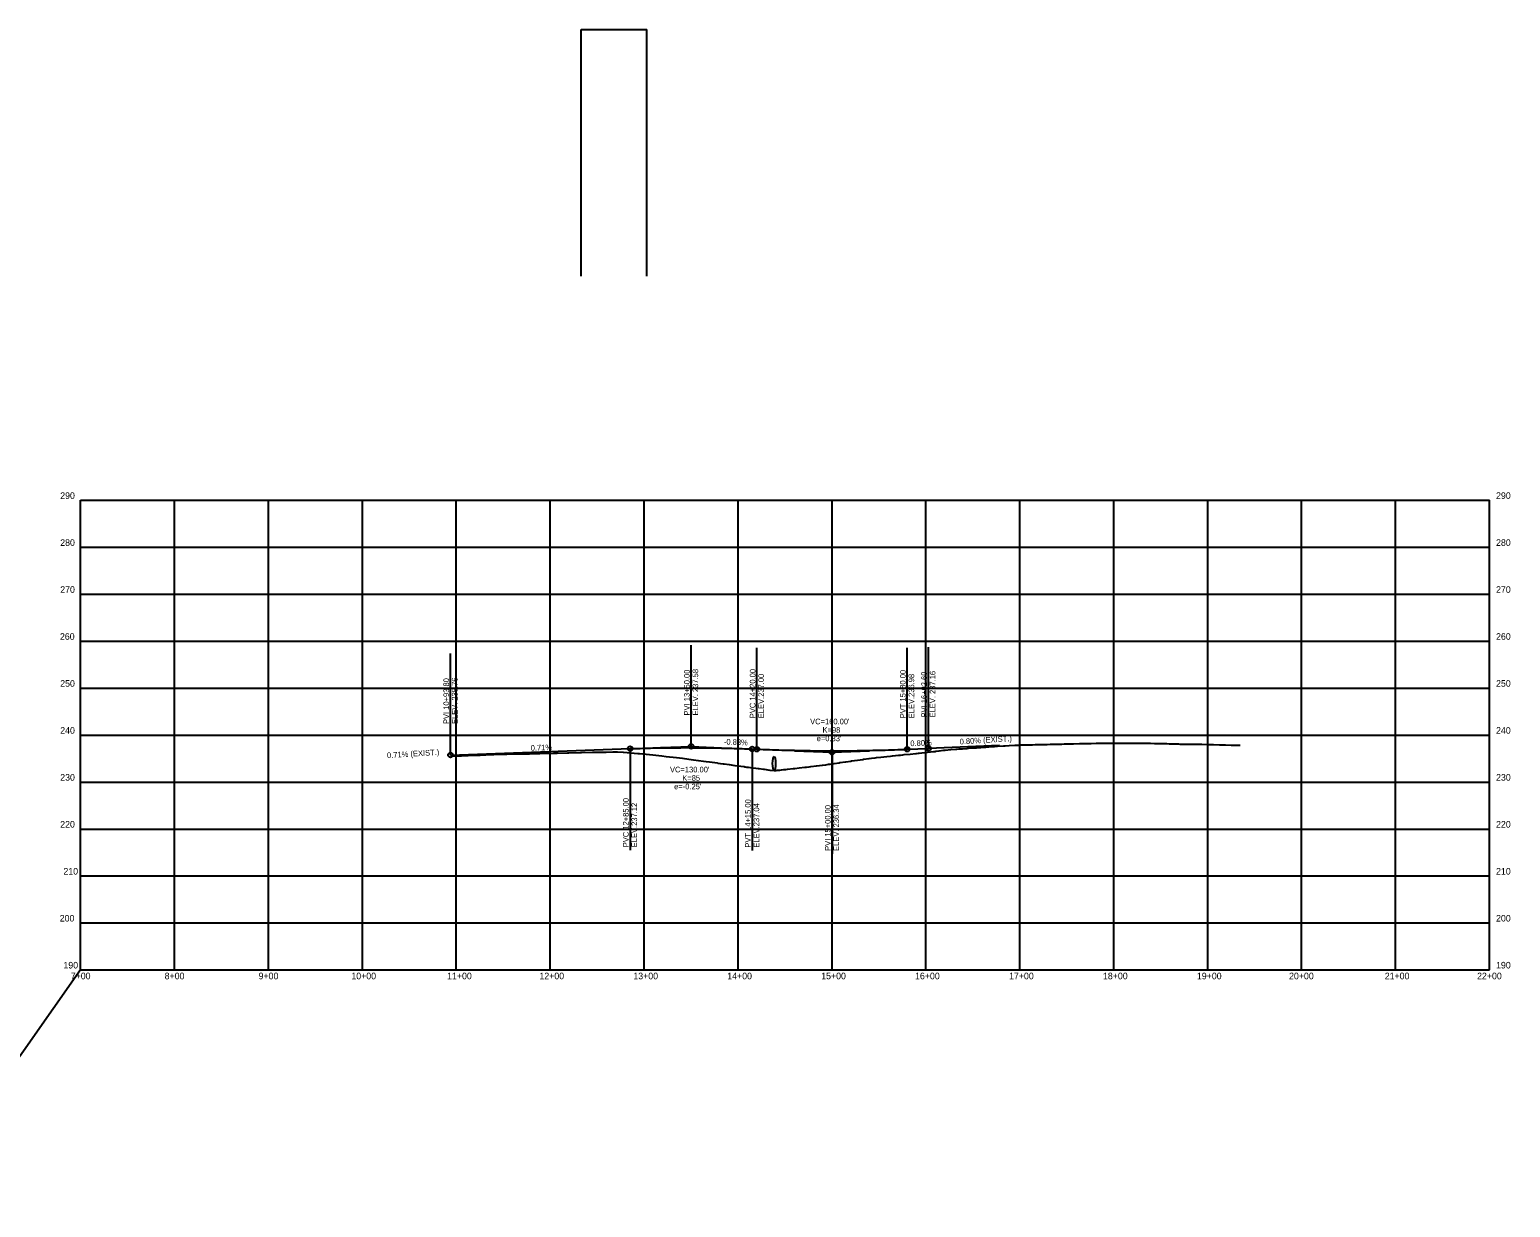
# Model space of a CAD drawing. Extents: x 1676565 to 1681112, y 227357 to 229815.
# Drawn here: x 1678113 to 1679690, y 227357 to 228611 of the extents above; entities that cross this region are included whole.
import ezdxf

# ---------------------------------------------------------------- set-up
doc = ezdxf.new("R2010")
doc.units = 0
for name, color, linetype in [('B_Steel', 7, 'Continuous'), ('R_Axis', 7, 'Continuous'), ('R_Axis Annot', 7, 'Continuous'), ('R_Exist Surface', 7, 'Continuous'), ('R_Grid', 7, 'Continuous'), ('R_Horz Alg Annot', 7, 'Continuous'), ('R_No Plot', 7, 'Continuous'), ('R_Vert Alg', 7, 'Continuous'), ('R_Vert Alg Annot', 7, 'Continuous'), ('R_Water', 7, 'Continuous')]:
    doc.layers.add(name, color=color, linetype=linetype)

msp = doc.modelspace()

# ---------------------------------------------------------------- linework, layer by layer
at = {"layer": 'B_Steel'}
for p, q in [((1678700.3, 228348.8), (1678700.3, 228611.2)), ((1678700.3, 228611.2), (1678770.3, 228611.2)), ((1678770.3, 228348.8), (1678770.3, 228611.2))]:
    msp.add_line(p, q, dxfattribs=at)
at = {"layer": 'R_Axis'}
for p, q in [((1678167.3, 227610), (1678167.3, 228110)), ((1679667.3, 227610), (1679667.3, 228110)), ((1678167.3, 227610), (1679667.3, 227610))]:
    msp.add_line(p, q, dxfattribs=at)
at = {"layer": 'R_Exist Surface'}
msp.add_lwpolyline([(1678561.1, 227837.6), (1678565.7, 227837.8), (1678573, 227838), (1678580.1, 227838.3), (1678586, 227838.5), (1678592.7, 227838.8), (1678598.9, 227839.1), (1678607.4, 227839.3), (1678617, 227839.7), (1678621, 227839.7), (1678628, 227839.9), (1678633.4, 227840), (1678638.4, 227840.1), (1678645.4, 227840.1), (1678656.1, 227840.4), (1678670.8, 227840.7), (1678674.7, 227840.8), (1678685.8, 227841), (1678687.2, 227841.1), (1678699.5, 227841.4), (1678699.7, 227841.4), (1678700.7, 227841.4), (1678712.2, 227841.7), (1678727, 227842), (1678734.1, 227842.2), (1678738.8, 227842.3), (1678744.9, 227841.8), (1678745.3, 227841.8), (1678760.7, 227840.5), (1678762.5, 227840.3), (1678776.4, 227839), (1678779.8, 227838.6), (1678786.2, 227837.9), (1678790.7, 227837.3), (1678801.8, 227836.1), (1678808, 227835.4), (1678814.7, 227834.4), (1678820, 227833.7), (1678830.4, 227832.4), (1678833.4, 227832), (1678837, 227831.5), (1678845.3, 227830.3), (1678845.7, 227830.2), (1678851.5, 227829.5), (1678852.6, 227829.4), (1678857.7, 227828.6), (1678863.9, 227827.7), (1678870.1, 227826.9), (1678873.9, 227826.4), (1678874.4, 227826.3), (1678874.9, 227826.2), (1678876.4, 227826), (1678878.4, 227825.7), (1678882.6, 227825.2), (1678886.2, 227824.8), (1678888.8, 227824.5), (1678889.6, 227824.4), (1678894.4, 227823.7), (1678895, 227823.7), (1678901.2, 227822.8), (1678905.6, 227822.3), (1678907.4, 227822.4), (1678908.4, 227822.5), (1678911.7, 227822.8), (1678913.7, 227823), (1678915.5, 227823.2), (1678918.2, 227823.5), (1678919.9, 227823.7), (1678926.1, 227824.3), (1678926.3, 227824.3), (1678927.8, 227824.6), (1678932.3, 227825), (1678938.5, 227825.7), (1678940.3, 227825.8), (1678943.1, 227826.3), (1678944.7, 227826.5), (1678950.9, 227827.3), (1678957.2, 227828.1), (1678960.6, 227828.5), (1678963.4, 227828.9), (1678965.5, 227829.2), (1678969.6, 227829.8), (1678975.1, 227830.5), (1678975.8, 227830.7), (1678981.7, 227831.5), (1678982, 227831.6), (1678987.3, 227832.3), (1678988.2, 227832.5), (1678994.5, 227833.3), (1679000.3, 227834.1), (1679000.7, 227834.2), (1679006.9, 227835), (1679009.3, 227835.3), (1679013.1, 227835.8), (1679014.8, 227836.1), (1679019.3, 227836.6), (1679025.5, 227837.2), (1679029.6, 227837.6), (1679031.7, 227837.9), (1679031.8, 227837.9), (1679038, 227838.5), (1679040.3, 227838.7), (1679042.8, 227839), (1679044.2, 227839.2), (1679050.4, 227839.8), (1679056.6, 227840.4), (1679057.1, 227840.4), (1679059.3, 227840.7), (1679060.1, 227840.8), (1679062.8, 227841.1), (1679069, 227841.8), (1679075.3, 227842.5), (1679077.2, 227842.7), (1679077.8, 227842.8), (1679081.5, 227843.3), (1679086, 227843.8), (1679086.8, 227843.9), (1679087, 227843.9), (1679087.7, 227843.9), (1679093.9, 227844.5), (1679099, 227844.9), (1679100.1, 227845), (1679102.5, 227845.2), (1679106.3, 227845.5), (1679111.2, 227845.9), (1679112.6, 227846), (1679117.7, 227846.3), (1679118.8, 227846.4), (1679121, 227846.6), (1679125, 227846.8), (1679125.7, 227846.9), (1679131.2, 227847.3), (1679137.4, 227847.8), (1679140.3, 227848), (1679141.9, 227848.1), (1679143.6, 227848.2), (1679149.9, 227848.6), (1679151.1, 227848.7), (1679151.5, 227848.7), (1679155.8, 227849), (1679156.1, 227849), (1679162, 227849.2), (1679162.3, 227849.3), (1679166.9, 227849.4), (1679168.5, 227849.5), (1679173.7, 227849.6), (1679174.7, 227849.6), (1679177.6, 227849.6), (1679180.9, 227849.8), (1679183.5, 227849.9), (1679187.2, 227849.9), (1679191.7, 227850), (1679193.4, 227850.1), (1679196.3, 227850.1), (1679199.6, 227850.2), (1679205.1, 227850.3), (1679205.8, 227850.3), (1679212, 227850.5), (1679214.4, 227850.6), (1679218.2, 227850.6), (1679221.7, 227850.7), (1679224.4, 227850.7), (1679230.7, 227850.9), (1679233.3, 227850.9), (1679236.9, 227851), (1679242, 227851.1), (1679243.1, 227851.2), (1679248.5, 227851.3), (1679249.3, 227851.3), (1679255.2, 227851.4), (1679255.5, 227851.4), (1679261.7, 227851.4), (1679265.4, 227851.5), (1679268, 227851.5), (1679269, 227851.5), (1679274.2, 227851.5), (1679280.4, 227851.5), (1679284.1, 227851.5), (1679286.6, 227851.5), (1679287.3, 227851.5), (1679292.8, 227851.5), (1679295.1, 227851.5), (1679299, 227851.4), (1679305.3, 227851.3), (1679306.3, 227851.3), (1679310.7, 227851.2), (1679311.5, 227851.2), (1679317.7, 227851), (1679322.1, 227851), (1679323.9, 227850.9), (1679326.1, 227850.8), (1679330.1, 227850.7), (1679336.3, 227850.6), (1679337.6, 227850.5), (1679342.6, 227850.5), (1679348.8, 227850.4), (1679355, 227850.3), (1679355.5, 227850.3), (1679359.5, 227850.2), (1679361.2, 227850.2), (1679367.4, 227850.1), (1679368.4, 227850), (1679372.6, 227849.9), (1679373.6, 227849.9), (1679379.8, 227849.8), (1679385.9, 227849.6), (1679386.1, 227849.6), (1679392.3, 227849.4), (1679396.5, 227849.3), (1679399.9, 227849.2), (1679402, 227849.1)], dxfattribs=at)
at = {"layer": 'R_Grid'}
for p, q in [((1678167.3, 228110), (1679667.3, 228110)), ((1678167.3, 228110), (1679667.3, 228110)), ((1678267.3, 227610), (1678267.3, 228110)), ((1678367.3, 227610), (1678367.3, 228110)), ((1678467.3, 227610), (1678467.3, 228110)), ((1678567.3, 227610), (1678567.3, 228110)), ((1678667.3, 227610), (1678667.3, 228110)), ((1678767.3, 227610), (1678767.3, 228110)), ((1678867.3, 227610), (1678867.3, 228110)), ((1678967.3, 227610), (1678967.3, 228110)), ((1679067.3, 227610), (1679067.3, 228110)), ((1679167.3, 227610), (1679167.3, 228110)), ((1679267.3, 227610), (1679267.3, 228110)), ((1679367.3, 227610), (1679367.3, 228110)), ((1679467.3, 227610), (1679467.3, 228110)), ((1679567.3, 227610), (1679567.3, 228110)), ((1678167.3, 228060), (1679667.3, 228060)), ((1678167.3, 228010), (1679667.3, 228010)), ((1678167.3, 227960), (1679667.3, 227960)), ((1678167.3, 227910), (1679667.3, 227910)), ((1678167.3, 227860), (1679667.3, 227860)), ((1678167.3, 227810), (1679667.3, 227810)), ((1678167.3, 227760), (1679667.3, 227760)), ((1678167.3, 227710), (1679667.3, 227710)), ((1678167.3, 227660), (1679667.3, 227660))]:
    msp.add_line(p, q, dxfattribs=at)
at = {"layer": 'R_Horz Alg Annot'}
msp.add_line((1678561.1, 227838.9), (1678561.1, 227838.8), dxfattribs=at)
at = {"layer": 'R_No Plot'}
msp.add_line((1678167.3, 227610), (1677989.4, 227357.1), dxfattribs=at)
at = {"layer": 'R_Vert Alg'}
for p, q in [((1678561.1, 227838.8), (1678752.3, 227845.6)), ((1678784.8, 227846.7), (1678817.3, 227847.9)), ((1678817.3, 227847.9), (1678849.8, 227846.6)), ((1678882.3, 227845.2), (1678887.3, 227845)), ((1678927.3, 227843.3), (1678967.3, 227841.7)), ((1678967.3, 227841.7), (1679007.3, 227843.3)), ((1679047.3, 227844.9), (1679069.9, 227845.8)), ((1679145.5, 227848.8), (1679069.9, 227845.8))]:
    msp.add_line(p, q, dxfattribs=at)
for points in [[(1678752.3, 227845.6), (1678755, 227845.7), (1678757.7, 227845.8), (1678760.4, 227845.9), (1678763.1, 227845.9), (1678765.8, 227846), (1678767.3, 227846.1)], [(1678767.3, 227846.1), (1678768.6, 227846.1), (1678771.3, 227846.2), (1678774, 227846.2), (1678776.7, 227846.3), (1678779.4, 227846.3), (1678782.1, 227846.4), (1678784.8, 227846.4), (1678787.5, 227846.5), (1678790.2, 227846.5), (1678792.9, 227846.5), (1678795.6, 227846.6), (1678798.3, 227846.6), (1678801.1, 227846.6), (1678803.8, 227846.6), (1678806.5, 227846.6), (1678809.2, 227846.7), (1678811.9, 227846.7), (1678814.6, 227846.7), (1678820, 227846.6), (1678822.7, 227846.6), (1678825.4, 227846.6), (1678828.1, 227846.6), (1678830.8, 227846.6), (1678833.6, 227846.5), (1678836.3, 227846.5), (1678839, 227846.4), (1678841.7, 227846.4), (1678844.4, 227846.4), (1678847.1, 227846.3), (1678849.8, 227846.2), (1678852.5, 227846.2), (1678855.2, 227846.1), (1678857.9, 227846), (1678860.6, 227846), (1678863.3, 227845.9), (1678866.1, 227845.8), (1678868.8, 227845.7), (1678871.5, 227845.6), (1678874.2, 227845.5), (1678876.9, 227845.4), (1678879.6, 227845.3), (1678882.3, 227845.2)], [(1678887.3, 227845), (1678890.6, 227844.9), (1678894, 227844.7), (1678897.3, 227844.6), (1678900.6, 227844.5), (1678904, 227844.4), (1678907.3, 227844.3), (1678910.6, 227844.2), (1678914, 227844.1), (1678917.3, 227844), (1678920.6, 227843.9), (1678924, 227843.8), (1678927.3, 227843.8), (1678930.6, 227843.7), (1678934, 227843.6), (1678937.3, 227843.6), (1678940.6, 227843.5), (1678944, 227843.5), (1678947.3, 227843.4), (1678950.6, 227843.4), (1678954, 227843.4), (1678957.3, 227843.4), (1678960.6, 227843.3), (1678964, 227843.3), (1678970.6, 227843.3), (1678974, 227843.3), (1678977.3, 227843.3), (1678980.6, 227843.4), (1678984, 227843.4), (1678987.3, 227843.4), (1678990.6, 227843.4), (1678994, 227843.5), (1678997.3, 227843.5), (1679000.6, 227843.6), (1679004, 227843.6), (1679007.3, 227843.7), (1679010.6, 227843.8), (1679014, 227843.8), (1679017.3, 227843.9), (1679020.6, 227844), (1679024, 227844.1), (1679027.3, 227844.2), (1679030.6, 227844.3), (1679034, 227844.4), (1679037.3, 227844.5), (1679040.6, 227844.6), (1679044, 227844.8), (1679047.3, 227844.9)]]:
    msp.add_lwpolyline(points, dxfattribs=at)
at = {"layer": 'R_Vert Alg Annot'}
for p, q in [((1678817.3, 227877.9), (1678817.3, 227955.9)), ((1678887.3, 227875), (1678887.3, 227953)), ((1679047.3, 227874.9), (1679047.3, 227952.9)), ((1679069.9, 227875.8), (1679069.9, 227953.8)), ((1678561.1, 227868.8), (1678561.1, 227946.8)), ((1678817.3, 227847.9), (1678817.3, 227877.9)), ((1678887.3, 227845), (1678887.3, 227875)), ((1679047.3, 227844.9), (1679047.3, 227874.9)), ((1679069.9, 227845.8), (1679069.9, 227875.8)), ((1678561.1, 227838.8), (1678561.1, 227868.8)), ((1678752.3, 227845.6), (1678752.3, 227815.6)), ((1678882.3, 227845.2), (1678882.3, 227815.2)), ((1678967.3, 227841.7), (1678967.3, 227811.7)), ((1678752.3, 227815.6), (1678752.3, 227737.6)), ((1678882.3, 227815.2), (1678882.3, 227737.2)), ((1678967.3, 227811.7), (1678967.3, 227733.7))]:
    msp.add_line(p, q, dxfattribs=at)
for centre in [(1678752.3, 227845.6), (1678817.3, 227847.9), (1678882.3, 227845.2), (1678887.3, 227845), (1678967.3, 227841.7), (1679047.3, 227844.9), (1679069.9, 227845.8), (1678561.1, 227838.8)]:
    msp.add_circle(centre, 2.5, dxfattribs=at)
at = {"layer": 'R_Water'}
msp.add_ellipse((1678905.6, 227829.8), major_axis=(0, 7.5), ratio=0.2, dxfattribs=at)

# ---------------------------------------------------------------- texts
at = {"layer": 'R_Axis Annot'}
for s, height, p in [('290', 7, (1678145.6, 228111.5)), ('290', 7, (1678145.6, 228111.5)), ('290', 7, (1679674.3, 228111.5)), ('290', 7, (1679674.3, 228111.5)), ('280', 7, (1678145.6, 228061.5)), ('280', 7, (1679674.3, 228061.5)), ('270', 7, (1678145.6, 228011.5)), ('270', 7, (1679674.3, 228011.5)), ('260', 7, (1678145.3, 227961.5)), ('260', 7, (1679674.3, 227961.5)), ('250', 7, (1678145.6, 227911.5)), ('250', 7, (1679674.3, 227911.5)), ('240', 7, (1678145.6, 227861.5)), ('240', 7, (1679674.3, 227861.5)), ('230', 7, (1678145.6, 227811.5)), ('230', 7, (1679674.3, 227811.5)), ('220', 7, (1678145.6, 227761.5)), ('220', 7, (1679674.3, 227761.5)), ('210', 7, (1678149, 227711.5)), ('210', 7, (1679674.3, 227711.5)), ('200', 7, (1678145.1, 227661.5)), ('200', 7, (1679674.3, 227661.5)), ('190', 7, (1678149, 227611.5)), ('7+00', 7, (1678156.8, 227600)), ('-', 0.0001, (1678167.3, 227610)), ('8+00', 7, (1678256.8, 227600)), ('9+00', 7, (1678356.8, 227600)), ('10+00', 7, (1678455.6, 227600)), ('11+00', 7, (1678557.5, 227600)), ('12+00', 7, (1678655.8, 227600)), ('13+00', 7, (1678755.8, 227600)), ('14+00', 7, (1678855.8, 227600)), ('15+00', 7, (1678955.8, 227600)), ('16+00', 7, (1679055.7, 227600)), ('17+00', 7, (1679155.8, 227600)), ('18+00', 7, (1679255.8, 227600)), ('19+00', 7, (1679355.8, 227600)), ('20+00', 7, (1679453.9, 227600)), ('21+00', 7, (1679555.8, 227600)), ('22+00', 7, (1679654.1, 227600)), ('190', 7, (1679674.3, 227611.5))]:
    msp.add_text(s, height=height, dxfattribs=at).set_placement(p)
at = {"layer": 'R_Vert Alg Annot'}
for s, rotation, p in [('PVI 13+50.00', 90, (1678815.8, 227880.9)), ('ELEV. 237.58', 90, (1678824.8, 227880.9)), ('PVC 14+20.00', 90, (1678885.8, 227878)), ('ELEV.237.00', 90, (1678894.8, 227878)), ('PVT 15+80.00', 90, (1679045.8, 227877.9)), ('ELEV.236.98', 90, (1679054.8, 227877.9)), ('PVI 16+02.60', 90, (1679068.4, 227878.8)), ('ELEV. 237.16', 90, (1679077.4, 227878.8)), ('PVI 10+93.80', 90, (1678559.6, 227871.8)), ('ELEV. 235.76', 90, (1678568.6, 227871.8)), ('0.80% (EXIST.)', 3.6821, (1679103.4, 227850)), ('0.71% (EXIST.)', 3.6821, (1678493.7, 227835.4)), ('0.71%', 2.0331, (1678646.6, 227843.3)), ('-0.83%', 357.6294, (1678852.1, 227850.1)), ('0.80%', 2.2906, (1679050.8, 227848.2)), ('PVC 12+85.00', 90, (1678750.8, 227740.6)), ('ELEV.237.12', 90, (1678759.8, 227740.6)), ('PVT 14+15.00', 90, (1678880.8, 227740.2)), ('ELEV.237.04', 90, (1678889.8, 227740.2)), ('PVI 15+00.00', 90, (1678965.8, 227736.7)), ('ELEV. 236.34', 90, (1678974.8, 227736.7))]:
    msp.add_text(s, height=6, rotation=rotation, dxfattribs=at).set_placement(p)
for s, p in [("VC=160.00'", (1678944, 227871.5)), ("e=0.33'", (1678951, 227853.5)), ('K=98', (1678957.2, 227862.5)), ("VC=130.00'", (1678794.8, 227820.3)), ('K=85', (1678807.9, 227811.3)), ("e=-0.25'", (1678799.2, 227802.3))]:
    msp.add_text(s, height=6, dxfattribs=at).set_placement(p)

doc.saveas('drawing.dxf')
